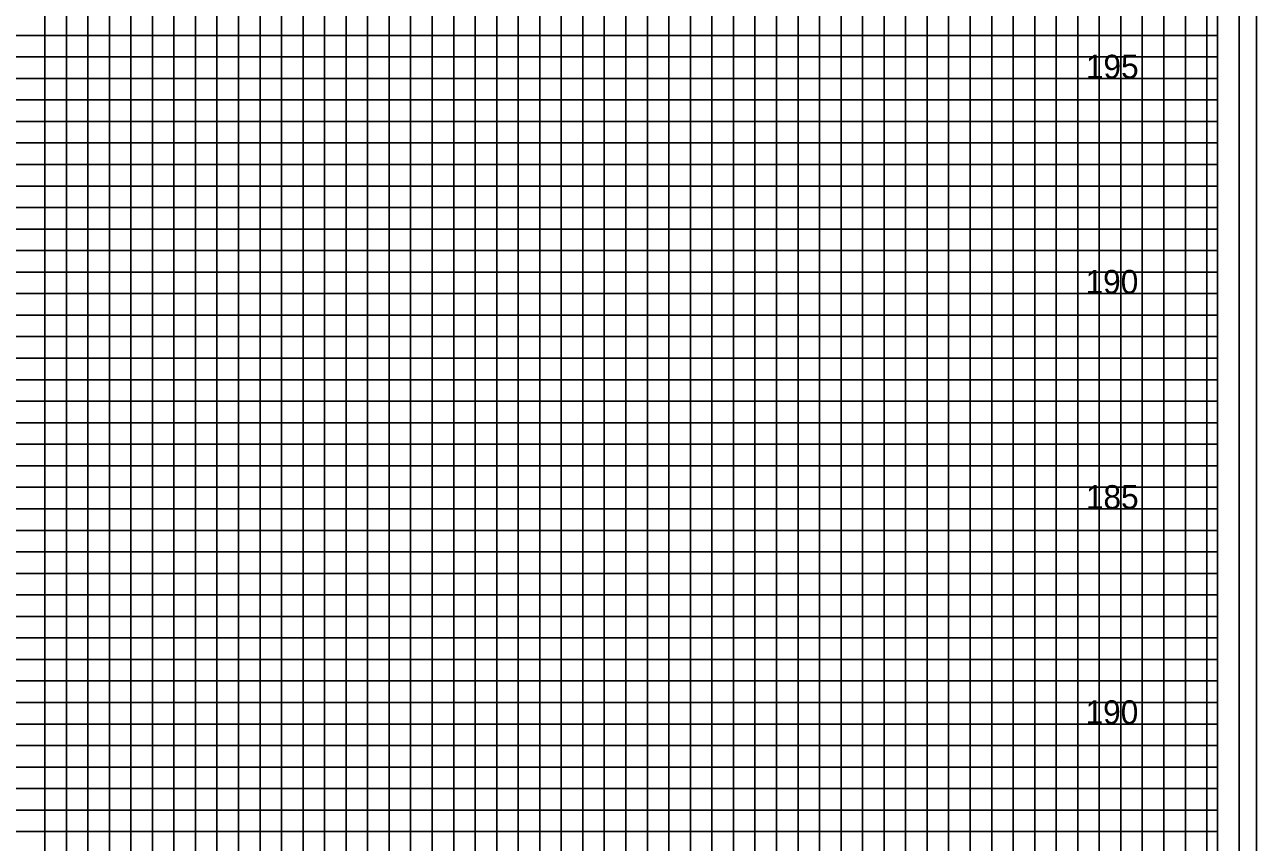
# Model space of a CAD drawing. Extents: x -4 to 103, y -2 to 138.
# Drawn here: x 74.78 to 103.4, y 32.25 to 51.25 of the extents above; entities that cross this region are included whole.
import ezdxf

# ---------------------------------------------------------------- set-up
doc = ezdxf.new("R2010")
doc.units = 0
for name, color, linetype in [('Old_Level_10', 7, 'Continuous'), ('Old_Level_5', 7, 'Continuous'), ('Old_Level_8', 7, 'Continuous'), ('Prop Dimension', 7, 'Continuous'), ('Prop XS SE Text', 7, 'Continuous'), ('Prop XS Subgrade Earthwork', 7, 'Continuous'), ('Prop XSC Text', 7, 'Continuous')]:
    doc.layers.add(name, color=color, linetype=linetype)

msp = doc.modelspace()

# ---------------------------------------------------------------- linework, layer by layer
at = {"layer": 'Old_Level_10'}
for p, q in [((91.25, 0), (91.25, 63.425)), ((93.75, 0), (93.75, 63.425)), ((96.25, 0), (96.25, 63.425)), ((98.75, 0), (98.75, 63.425)), ((101.25, 0), (101.25, 63.425)), ((76.25, 0), (76.25, 62)), ((78.75, 0), (78.75, 62)), ((81.25, 0), (81.25, 62)), ((83.75, 0), (83.75, 62)), ((86.25, 0), (86.25, 62)), ((88.75, 0), (88.75, 62)), ((0, 50), (102.5, 50)), ((0, 47.5), (102.5, 47.5)), ((0, 45), (102.5, 45)), ((0, 42.5), (102.5, 42.5)), ((0, 40), (102.5, 40)), ((0, 37.5), (102.5, 37.5)), ((0, 35), (102.5, 35)), ((0, 32.5), (102.5, 32.5))]:
    msp.add_line(p, q, dxfattribs=at)
at = {"layer": 'Old_Level_5'}
msp.add_lwpolyline([(103.4, 67.4), (-3.5, 67.4), (-3.5, -2.425), (103.4, -2.425)], close=True, dxfattribs=at)
at = {"layer": 'Old_Level_8'}
for points in [[(91.25, 0), (91.25, 63.425), (93.75, 63.425), (93.75, 0)], [(96.25, 0), (96.25, 63.425), (98.75, 63.425), (98.75, 0)], [(101.25, 0), (101.25, 63.425)], [(76.25, 0), (76.25, 62), (78.75, 62), (78.75, 0)], [(81.25, 0), (81.25, 62), (83.75, 62), (83.75, 0)], [(86.25, 0), (86.25, 62), (88.75, 62), (88.75, 0)], [(0, 47.5), (102.5, 47.5), (102.5, 50), (0, 50)], [(0, 42.5), (102.5, 42.5), (102.5, 45), (0, 45)], [(0, 37.5), (102.5, 37.5), (102.5, 40), (0, 40)], [(0, 32.5), (102.5, 32.5), (102.5, 35), (0, 35)]]:
    msp.add_lwpolyline(points, dxfattribs=at)
at = {"layer": 'Prop Dimension'}
for points in [[(90.25, 0), (90.25, 63.425), (90.75, 63.425), (90.75, 0)], [(91.75, 0), (91.75, 63.425), (92.25, 63.425), (92.25, 0)], [(92.75, 0), (92.75, 63.425), (93.25, 63.425), (93.25, 0)], [(94.25, 0), (94.25, 63.425), (94.75, 63.425), (94.75, 0)], [(95.25, 0), (95.25, 63.425), (95.75, 63.425), (95.75, 0)], [(96.75, 0), (96.75, 63.425), (97.25, 63.425), (97.25, 0)], [(97.75, 0), (97.75, 63.425), (98.25, 63.425), (98.25, 0)], [(99.25, 0), (99.25, 63.425), (99.75, 63.425), (99.75, 0)], [(100.25, 0), (100.25, 63.425)], [(100.25, 63.425), (100.75, 63.425), (100.75, 0), (101.75, 0), (101.75, 63.425), (102.25, 63.425), (102.25, 0)], [(75.25, 0), (75.25, 62), (75.75, 62), (75.75, 0)], [(76.75, 0), (76.75, 62), (77.25, 62), (77.25, 0)], [(77.75, 0), (77.75, 62), (78.25, 62), (78.25, 0)], [(79.25, 0), (79.25, 62), (79.75, 62), (79.75, 0)], [(80.25, 0), (80.25, 62), (80.75, 62), (80.75, 0)], [(81.75, 0), (81.75, 62), (82.25, 62), (82.25, 0)], [(82.75, 0), (82.75, 62), (83.25, 62), (83.25, 0)], [(84.25, 0), (84.25, 62), (84.75, 62), (84.75, 0)], [(85.25, 0), (85.25, 62), (85.75, 62), (85.75, 0)], [(86.75, 0), (86.75, 62), (87.25, 62), (87.25, 0)], [(87.75, 0), (87.75, 62), (88.25, 62), (88.25, 0)], [(89.25, 0), (89.25, 62), (89.75, 62), (89.75, 0)], [(0, 50.5), (102.5, 50.5), (102.5, 51), (0, 51)], [(0, 49), (102.5, 49), (102.5, 49.5), (0, 49.5)], [(0, 48), (102.5, 48), (102.5, 48.5), (0, 48.5)], [(0, 46.5), (102.5, 46.5), (102.5, 47), (0, 47)], [(0, 45.5), (102.5, 45.5), (102.5, 46), (0, 46)], [(0, 44), (102.5, 44), (102.5, 44.5), (0, 44.5)], [(0, 43), (102.5, 43), (102.5, 43.5), (0, 43.5)], [(0, 41.5), (102.5, 41.5), (102.5, 42), (0, 42)], [(0, 40.5), (102.5, 40.5), (102.5, 41), (0, 41)], [(0, 39), (102.5, 39), (102.5, 39.5), (0, 39.5)], [(0, 38), (102.5, 38), (102.5, 38.5), (0, 38.5)], [(0, 36.5), (102.5, 36.5), (102.5, 37), (0, 37)], [(0, 35.5), (102.5, 35.5), (102.5, 36), (0, 36)], [(0, 34), (102.5, 34), (102.5, 34.5), (0, 34.5)], [(0, 33), (102.5, 33), (102.5, 33.5), (0, 33.5)]]:
    msp.add_lwpolyline(points, dxfattribs=at)
at = {"layer": 'Prop XS SE Text'}
msp.add_lwpolyline([(103, 66), (-2.8, 66), (-2.8, -1), (103, -1)], close=True, dxfattribs=at)
at = {"layer": 'Prop XSC Text'}
msp.add_lwpolyline([(102.5, 65), (0, 65), (0, 0), (102.5, 0)], close=True, dxfattribs=at)

# ---------------------------------------------------------------- texts
at = {"layer": 'Prop XS Subgrade Earthwork'}
for s, p in [('195', (99.438, 50)), ('190', (99.43, 45)), ('185', (99.438, 40)), ('190', (99.43, 35))]:
    msp.add_text(s, height=0.55, dxfattribs=at).set_placement(p)

doc.saveas('drawing.dxf')
